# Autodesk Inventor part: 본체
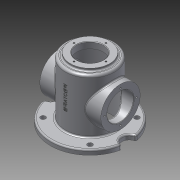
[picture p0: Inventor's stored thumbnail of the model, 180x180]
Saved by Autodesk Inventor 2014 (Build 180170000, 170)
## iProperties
Created: 2018-04
Part Number: 본체
Material: 알루미늄 6061
Document SubType Name: Modeling
Designer: OA62
Density: 2.71 g/cm^3
Appearance: 알루미늄 - 평지
Mass: 1147.09 g
Surface Area: 1195.3 cm^2
Volume: 423.281 cm^3
Author: OA62
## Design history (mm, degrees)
sketch "스케치1"
  geometry: L1 (0, 0)-(80, 0); L2 (80, 0)-(80, 133); L3 (80, 133)-(0, 133); L4 (0, 133)-(0, 0); L5 (50, 0)-(50, 8); L6 (50, 8)-(80, 8); L7 (80, 18)-(50, 18); L8 (50, 18)-(50, 128); L9 (50, 128)-(40, 128); L10 (40, 128)-(40, 133); L11 (27, 120)-(27, 133); L12 (27, 120)-(0, 120); 1 further point
  constraints: 24 end point, 6 point on line, 5 perpendicular, 4 parallel, 1 horizontal, 1 midpoint
  dimensions: "d0" = 80 distance of L3.end L2.end; "d1" = 133 distance of L1.end L2.end; "d2" = 50 distance between parallel lines of L4 L5; "d3" = 8 distance between parallel lines of L1 L6; "d4" = 10 distance between parallel lines of L7 L6; "d5" = 50 distance between parallel lines of L4 L8; "d6" = 40 distance between parallel lines of L4 L10; "d7" = 5 distance between parallel lines of L3 L9; "d10" = 27 distance between parallel lines of L4 L11; "d30" = 13 distance between parallel lines of L3 L12
revolve "회전1" sketch "스케치1" stored, may be unused: angle "d12" = 90 deg
sketch "스케치2"
  geometry: C1 r 50 at (0, 0) reference; C2 r 15 at (-80, 0); C3 r 15 at (80, 0); A1 r 80 centre (0, 0) between (-80, 0) and (80, 0) reference
  constraints: 2 centre point, 2 horizontal alignment, 2 point on circle
  dimensions: "d13" = 30 diameter of C2; "d14" = 30 diameter of C3
extrude "돌출1" cut sketch "스케치2" stored distance "d15" = 10; taper "d16" = 0 deg
sketch "스케치3"
  geometry: L1 (47.73, -47.73)-(-47.73, 47.73); L2 (-47.73, -47.73)-(47.73, 47.73); L3 (0, 0)-(0, 67.5); C1 r 50 at (0, 0) reference; A1 r 67.5 centre (0, 0) between (-47.73, 47.73) and (47.73, 47.73); 4 further points
  constraints: 6 end point, 5 coincident, 5 point on circle, 2 midpoint, 1 centre point, 1 vertical
  dimensions: "d17" = 135 diameter of A1; "d18" = 45 deg angle of L3 L1; "d19" = 90 deg angle of L2 L1
hole "구멍1" sketch "스케치3" at (-47.73, 47.73), (47.73, 47.73), (-47.73, -47.73), (47.73, -47.73) diameter "d20" = 10; stored, may be unused: countersink angle "d24" = 90 deg, drill point angle "d26" = 118 deg; dims "d21" = 6, "d22" = 4, "d23" = 2, "d25" = 8
sketch "스케치4"
  geometry: C1 r 40 at (68, 0); 1 further point
  constraints: 1 centre point, 1 horizontal alignment
  dimensions: "d27" = 80 diameter of C1; "d31" = 68 distance of point (0, 0) C1.centre
extrude "돌출2" join sketch "스케치4" stored distance "d32" = 124; taper "d33" = 0 deg
sketch "스케치5"
  geometry: C1 r 40 at (0, 0) reference; C2 r 27 at (0, 0); 1 further point
  constraints: 1 centre point, 1 coincident
  dimensions: "d34" = 54 diameter of C2
extrude "돌출3" cut sketch "스케치5" distance "d35" = 124; taper "d36" = 0 deg
sketch "스케치6"
  geometry: C1 r 50 at (0, 0) reference; C2 r 45 at (0, 0)
  constraints: 1 centre point, 1 coincident
  dimensions: "d37" = 90 diameter of C2
extrude "돌출4" cut sketch "스케치6" distance "d38" = 120; taper "d39" = 0 deg
sketch "스케치7"
  geometry: C1 r 27 at (0, 0) reference; 1 further point
  constraints: 1 horizontal alignment
  dimensions: "d40" = 32.5 distance of point (32.5, 0) C1.centre
hole "구멍2" sketch "스케치7" at (32.5, 0) diameter "d41" = 3.242; stored, may be unused: countersink angle "d45" = 90 deg, drill point angle "d47" = 118 deg; dims "d42" = 8, "d43" = 4, "d44" = 2, "d46" = 10
sketch "스케치8"
  geometry: C1 r 27 at (0, 0) reference; 2 further points
  constraints: 1 vertical alignment
  dimensions: "d51" = 32.5 distance of C1.centre point (0, 32.5)
hole "구멍3" sketch "스케치8" at (0, 32.5) diameter "d52" = 3.242; stored, may be unused: countersink angle "d56" = 90 deg, drill point angle "d58" = 118 deg; dims "d53" = 8, "d54" = 4, "d55" = 2, "d57" = 10
node "작업 평면1"
sketch "스케치9"
  geometry: L1 (-78.594, 8)-(78.594, 8) reference; 2 further points
  constraints: 1 vertical alignment, 1 other
  dimensions: "d63" = 70 distance from line of L1 point (0, 78)
feature "엠보싱1" sketch "스케치9" dims "d0" = 80, "d1" = 133, "d2" = 50, "d3" = 8, "d4" = 10, "d5" = 50, "d6" = 40, "d7" = 5, "d10" = 27, "d30" = 13, "d64" = 0.5, "d65" = 0
fillet "모깎기1" dims "d66" = 5
fillet "모깎기2" dims "d67" = 3
fillet "모깎기3" dims "d68" = 3
chamfer "모따기1" distance "d70" = 1; stored, may be unused: second distance "d71" = 2, angle "d72" = 45 deg
node "솔리드1"
pattern_circular "원형 패턴1" dims angle "d49" = 360 deg
pattern_circular "원형 패턴2" dims angle "d60" = 360 deg
mirror "대칭1"
